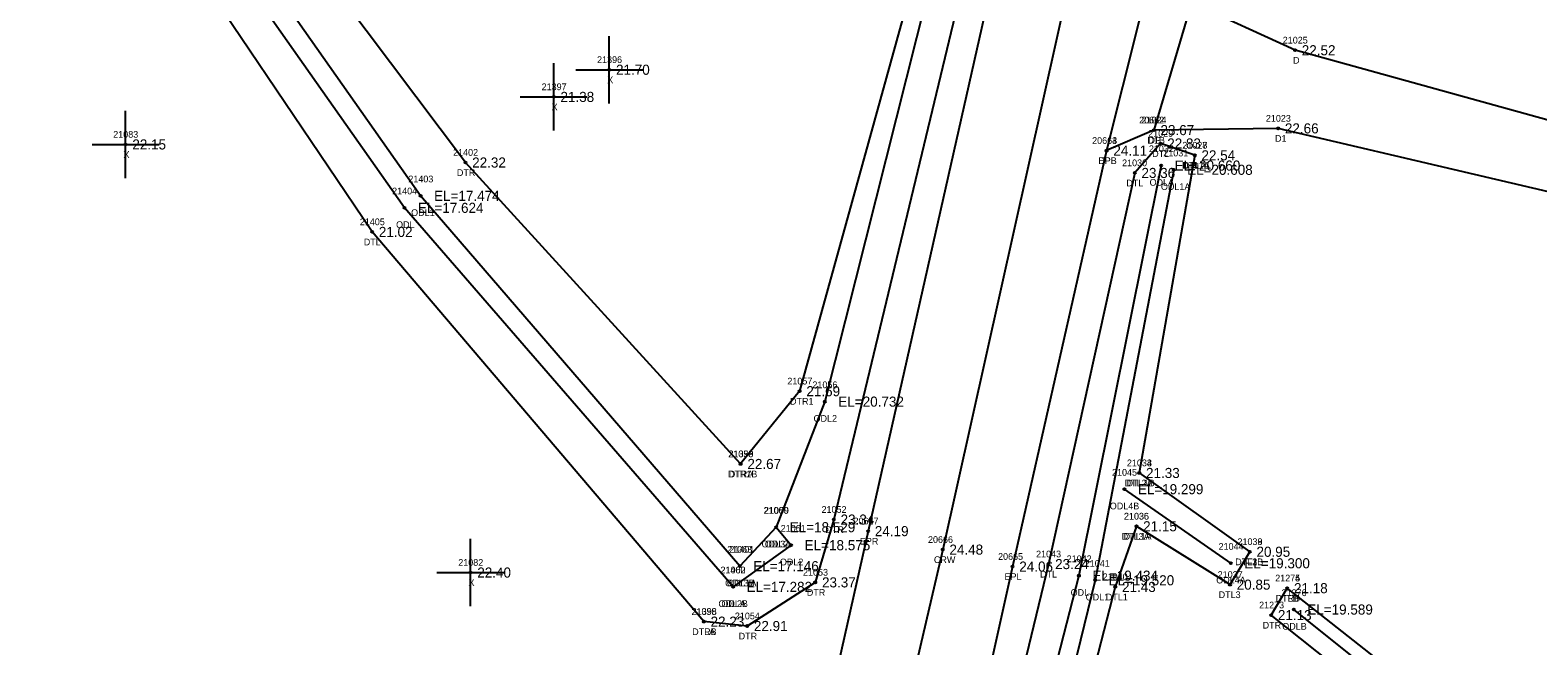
# Model space of a CAD drawing. Extents: x 2655177 to 2656219, y 761780 to 764748.
# Drawn here: x 2655371.8 to 2655596.2, y 762312.5 to 762404.1 of the extents above; entities that cross this region are included whole.
import ezdxf

# ---------------------------------------------------------------- set-up
doc = ezdxf.new("R2010")
doc.units = 0
for name, color, linetype in [('RD_DTM_BkLn1', 7, 'Continuous'), ('RD_EX_Driveway', 7, 'Continuous'), ('RD_EX_Driveway_txCode', 7, 'Continuous'), ('RD_EX_H2O', 7, 'Continuous'), ('RD_EX_H2O_txCode', 7, 'Continuous'), ('RD_EX_Misc', 7, 'Continuous'), ('RD_EX_Misc_txCode', 7, 'Continuous'), ('RD_EX_Road', 7, 'Continuous'), ('RD_EX_Road_txCode', 7, 'Continuous'), ('RD_EX_TX_Driveway_ELEV', 7, 'Continuous'), ('RD_EX_TX_H2O_ELEV', 7, 'Continuous'), ('RD_EX_TX_Misc_ELEV', 7, 'Continuous'), ('RD_EX_TX_Road_ELEV', 7, 'Continuous'), ('RD_HC_Survey_ELEV', 7, 'Continuous'), ('RD_HC_Survey_txCode', 7, 'Continuous'), ('RD_SMD_Locator', 7, 'Continuous')]:
    doc.layers.add(name, color=color, linetype=linetype)

msp = doc.modelspace()

# ---------------------------------------------------------------- linework, layer by layer
at = {"layer": 'RD_DTM_BkLn1'}
msp.add_lwpolyline([(2655711.06, 763230.3), (2655703.38, 763195.9), (2655681.97, 763099.65), (2655659.44, 762998.39), (2655637.72, 762903.26), (2655615.94, 762806.28), (2655593.94, 762710.45), (2655572.67, 762616.37), (2655551.12, 762519.58), (2655528.83, 762422.13), (2655507.58, 762326.81), (2655486.01, 762234.2), (2655464.77, 762141.12), (2655442.2, 762047.28), (2655420.99, 761952.95), (2655398.79, 761855.74), (2655384.11, 761791.21)], dxfattribs=at)
at = {"layer": 'RD_EX_Driveway'}
for points in [[(2655539.15, 762414.81), (2655544.59, 762408.15), (2655538.99, 762389.2), (2655531.98, 762386.15)], [(2655618.28, 762384.97), (2655560.02, 762401.08), (2655544.59, 762408.15)], [(2655615.95, 762375.77), (2655557.51, 762389.46), (2655538.99, 762389.2)]]:
    msp.add_lwpolyline(points, dxfattribs=at)
at = {"layer": 'RD_EX_H2O'}
for p, q in [((2655545.09, 762385.45), (2655536.84, 762338.21)), ((2655536.84, 762338.21), (2655553.28, 762326.49)), ((2655550.47, 762324.78), (2655534.62, 762335.8)), ((2655482.81, 762330.14), (2655477.37, 762324.35))]:
    msp.add_line(p, q, dxfattribs=at)
for points in [[(2655472.03, 762316.1), (2655422.66, 762374.06), (2655364.12, 762460.66), (2655307.09, 762538.82), (2655256.59, 762623.14), (2655196.27, 762713.84), (2655205.8, 762720.91)], [(2655477.51, 762339.55), (2655436.55, 762384.38), (2655373.64, 762467.97), (2655320.48, 762547.58), (2655269.92, 762633.7), (2655205.8, 762720.91)], [(2655476.38, 762321.27), (2655427.48, 762377.64), (2655367.29, 762463.1), (2655312.28, 762542.21), (2655260.75, 762626.43), (2655202.15, 762714.73)], [(2655477.37, 762324.35), (2655429.88, 762379.43), (2655369.67, 762464.93), (2655315.46, 762544.29), (2655265.61, 762630.28), (2655205.06, 762716.28)], [(2655543.55, 762560.68), (2655539.34, 762565), (2655535.47, 762561.26), (2655533.61, 762546.63), (2655528.16, 762524.75), (2655507.6, 762427.4), (2655486.29, 762350.37), (2655477.51, 762339.55)], [(2655543.55, 762560.68), (2655534.37, 762523.92), (2655514.09, 762425.76), (2655491.38, 762331.28), (2655488.62, 762321.94), (2655478.48, 762315.45), (2655472.03, 762316.1)], [(2655538.37, 762560.08), (2655529.54, 762524.52), (2655509.74, 762426.95), (2655490.05, 762348.82), (2655482.81, 762330.14), (2655485.04, 762327.47), (2655476.38, 762321.27)], [(2655545.09, 762385.45), (2655540, 762387.21), (2655536.16, 762382.83), (2655523.31, 762324.66), (2655511.9, 762277.49)], [(2655540.11, 762383.93), (2655527.86, 762322.94), (2655515.9, 762276.48)], [(2655541.96, 762383.3), (2655530.27, 762322.25), (2655518.81, 762275.44)], [(2655536.41, 762330.28), (2655533.27, 762321.26), (2655520.61, 762272.2), (2655514.15, 762273.86), (2655511.9, 762277.49)], [(2655536.41, 762330.28), (2655550.34, 762321.6), (2655553.28, 762326.49)], [(2655458.25, 762004.65), (2655489.16, 762003.6), (2655538.42, 762005.59), (2655556.05, 762013.17), (2655587.88, 762051.39), (2655643.4, 762074.04), (2655655.85, 762091.76), (2655681.86, 762140.14), (2655683.72, 762146.53), (2655664.39, 762201.23), (2655621.98, 762271.36), (2655558.86, 762321.08)], [(2655459.71, 762010.57), (2655488.92, 762008.22), (2655537.08, 762011.25), (2655554.9, 762018.55), (2655583.72, 762054.68), (2655639.44, 762078.76), (2655651.66, 762094.07), (2655673.82, 762140.27), (2655676.22, 762150.22), (2655658.16, 762196.88), (2655618.83, 762267.48), (2655556.47, 762317.07), (2655558.86, 762321.08)], [(2655456.91, 762008.75), (2655489.44, 762005.64), (2655537.92, 762008.34), (2655555.32, 762016.59), (2655585.73, 762052.79), (2655641.23, 762076.72), (2655654.31, 762091.55), (2655679.19, 762140.68), (2655679.13, 762150.47), (2655660.06, 762199), (2655620.4, 762269.42), (2655559.84, 762317.9)]]:
    msp.add_lwpolyline(points, dxfattribs=at)
at = {"layer": 'RD_EX_Misc'}
for p, q in [((2655457.96, 762393.18), (2655457.96, 762403.18)), ((2655449.69, 762389.14), (2655449.69, 762399.14)), ((2655452.96, 762398.18), (2655462.96, 762398.18)), ((2655444.69, 762394.14), (2655454.69, 762394.14)), ((2655385.97, 762382.07), (2655385.97, 762392.07)), ((2655380.97, 762387.07), (2655390.97, 762387.07)), ((2655437.31, 762318.4), (2655437.31, 762328.4)), ((2655432.31, 762323.4), (2655442.31, 762323.4))]:
    msp.add_line(p, q, dxfattribs=at)
at = {"layer": 'RD_EX_Road'}
for points in [[(2655700.99, 763232.28), (2655693.55, 763198.57), (2655671.65, 763102.04), (2655649.04, 763001.06), (2655627.27, 762906.23), (2655605, 762809.37), (2655598.99, 762783.09), (2655583.65, 762714.14), (2655561.97, 762618.32), (2655556.36, 762593.84), (2655548.11, 762557.14), (2655540.1, 762522.48), (2655518.03, 762425.04), (2655496.48, 762329.56), (2655475.55, 762236.62), (2655473.2, 762226.14), (2655466.57, 762197.5), (2655460.06, 762168.16), (2655454.26, 762143.78), (2655432.5, 762049.88), (2655410.7, 761955.51), (2655388.17, 761858.43), (2655373.5, 761793.95)], [(2655576.46, 762583.32), (2655561.41, 762517.24), (2655539.15, 762414.81), (2655531.98, 762386.15), (2655517.98, 762324.29), (2655508.17, 762280.15), (2655501.46, 762251.6), (2655496.92, 762232.09), (2655477.2, 762144.97), (2655472.14, 762122.52), (2655453.74, 762045.1), (2655431.79, 761949.92), (2655409.76, 761853.25), (2655401.25, 761816.42), (2655394.61, 761787.37)]]:
    msp.add_lwpolyline(points, dxfattribs=at)
at = {"layer": 'RD_SMD_Locator'}
for centre in [(2655560.02, 762401.08), (2655457.96, 762398.18), (2655449.69, 762394.14), (2655538.99, 762389.2), (2655538.99, 762389.2), (2655557.51, 762389.46), (2655385.97, 762387.07), (2655540, 762387.21), (2655531.98, 762386.15), (2655531.98, 762386.15), (2655545.09, 762385.45), (2655545.09, 762385.45), (2655436.55, 762384.38), (2655536.16, 762382.83), (2655540.11, 762383.93), (2655541.96, 762383.3), (2655429.88, 762379.43), (2655427.48, 762377.64), (2655422.66, 762374.06), (2655486.29, 762350.37), (2655490.05, 762348.82), (2655477.51, 762339.55), (2655477.51, 762339.55), (2655536.84, 762338.21), (2655536.84, 762338.21), (2655534.62, 762335.8), (2655491.38, 762331.28), (2655482.81, 762330.14), (2655482.81, 762330.14), (2655496.48, 762329.56), (2655536.41, 762330.28), (2655536.41, 762330.28), (2655485.04, 762327.47), (2655507.58, 762326.81), (2655553.28, 762326.49), (2655553.28, 762326.49), (2655477.37, 762324.35), (2655477.37, 762324.35), (2655517.98, 762324.29), (2655523.31, 762324.66), (2655550.47, 762324.78), (2655437.31, 762323.4), (2655488.62, 762321.94), (2655527.86, 762322.94), (2655530.27, 762322.25), (2655476.38, 762321.27), (2655476.38, 762321.27), (2655533.27, 762321.26), (2655550.34, 762321.6), (2655558.86, 762321.08), (2655558.86, 762321.08), (2655559.84, 762317.9), (2655472.03, 762316.1), (2655472.03, 762316.1), (2655478.48, 762315.45), (2655556.47, 762317.07)]:
    msp.add_circle(centre, 0.15, dxfattribs=at)

# ---------------------------------------------------------------- texts
at = {"layer": 'RD_EX_Driveway_txCode'}
for s, p in [('21025', (2655558.19, 762402.08)), ('D', (2655559.72, 762399.08)), ('21023', (2655555.68, 762390.46)), ('20662', (2655536.82, 762390.2)), ('21024', (2655537.16, 762390.2)), ('20663', (2655529.82, 762387.15)), ('D1B', (2655538.05, 762387.2)), ('DP', (2655538.21, 762387.2)), ('D1', (2655557.04, 762387.46)), ('DPB', (2655530.73, 762384.15))]:
    msp.add_text(s, height=1, dxfattribs=at).set_placement(p)
at = {"layer": 'RD_EX_H2O_txCode'}
for s, p in [('21029', (2655538.17, 762388.21)), ('21032', (2655538.27, 762385.93)), ('21027', (2655543.25, 762386.45)), ('21028', (2655543.25, 762386.45)), ('21402', (2655434.71, 762385.38)), ('21030', (2655534.28, 762383.83)), ('DTL', (2655538.76, 762385.21)), ('21031', (2655540.41, 762385.3)), ('21403', (2655428.05, 762381.43)), ('DTR', (2655435.28, 762382.38)), ('DTL1A', (2655543.19, 762383.45)), ('DTLA', (2655543.35, 762383.45)), ('21404', (2655425.64, 762379.64)), ('DTL', (2655534.91, 762380.83)), ('ODLA', (2655538.37, 762380.93)), ('ODL1A', (2655540.06, 762380.3)), ('21405', (2655420.83, 762375.06)), ('ODL1', (2655428.47, 762376.43)), ('ODL', (2655426.23, 762374.64)), ('DTL', (2655421.42, 762372.06)), ('21057', (2655484.46, 762351.37)), ('21056', (2655488.19, 762350.82)), ('DTR1', (2655484.86, 762348.37)), ('ODL2', (2655488.36, 762345.82)), ('21058', (2655475.67, 762340.55)), ('21399', (2655475.71, 762340.55)), ('21033', (2655535, 762339.21)), ('21034', (2655535, 762339.21)), ('DTR1B', (2655475.6, 762337.55)), ('DTRA', (2655475.75, 762337.55)), ('21045', (2655532.78, 762337.8)), ('DTL2A', (2655534.66, 762336.21)), ('DTL1B', (2655534.95, 762336.21)), ('21060', (2655480.91, 762332.14)), ('21059', (2655480.98, 762332.14)), ('21052', (2655489.55, 762332.28)), ('ODL4B', (2655532.45, 762332.8)), ('21036', (2655534.55, 762331.28)), ('21035', (2655534.57, 762331.28)), ('21061', (2655483.47, 762329.47)), ('DTR', (2655490.11, 762329.28)), ('DTL3A', (2655534.22, 762328.28)), ('DTL1A', (2655534.51, 762328.28)), ('21063', (2655475.51, 762326.35)), ('21401', (2655475.82, 762326.35)), ('ODL3A', (2655480.63, 762327.14)), ('ODL2', (2655481.12, 762327.14)), ('21043', (2655521.48, 762325.66)), ('21044', (2655548.64, 762326.78)), ('21038', (2655551.45, 762327.49)), ('21039', (2655551.45, 762327.49)), ('21400', (2655474.5, 762323.27)), ('21062', (2655474.52, 762323.27)), ('ODL2', (2655483.35, 762324.47)), ('21042', (2655526.03, 762324.94)), ('21041', (2655528.72, 762324.25)), ('DTL2B', (2655551.12, 762324.49)), ('DTL3B', (2655551.12, 762324.49)), ('ODL3B', (2655475.2, 762321.35)), ('ODL1A', (2655475.47, 762321.35)), ('21053', (2655486.79, 762322.94)), ('DTL', (2655522.07, 762322.66)), ('21040', (2655531.39, 762322.26)), ('ODL4A', (2655548.29, 762321.78)), ('21037', (2655548.51, 762322.6)), ('21274', (2655557.07, 762322.08)), ('21275', (2655557.07, 762322.08)), ('DTR', (2655487.36, 762319.94)), ('ODL', (2655526.62, 762319.94)), ('ODL1', (2655528.86, 762319.25)), ('DTL1', (2655531.86, 762319.26)), ('DTL3', (2655548.65, 762319.6)), ('DTRB', (2655557.12, 762319.08)), ('DTLB', (2655557.15, 762319.08)), ('21276', (2655558.02, 762319.9)), ('21055', (2655470.19, 762317.1)), ('21398', (2655470.23, 762317.1)), ('ODL2B', (2655474.21, 762318.27)), ('ODLA', (2655474.65, 762318.27)), ('21054', (2655476.65, 762316.45)), ('21273', (2655554.67, 762318.07)), ('DTR', (2655555.2, 762315.07)), ('ODLB', (2655558.12, 762314.9)), ('DTRB', (2655470.29, 762314.1)), ('DTLA', (2655470.3, 762314.1)), ('DTR', (2655477.21, 762313.45))]:
    msp.add_text(s, height=1, dxfattribs=at).set_placement(p)
at = {"layer": 'RD_EX_Misc_txCode'}
for s, p in [('21396', (2655456.14, 762399.18)), ('21397', (2655447.89, 762395.14)), ('X', (2655457.65, 762396.18)), ('X', (2655449.37, 762392.14)), ('21083', (2655384.13, 762388.07)), ('X', (2655385.65, 762385.07)), ('21082', (2655435.48, 762324.4)), ('X', (2655437, 762321.4))]:
    msp.add_text(s, height=1, dxfattribs=at).set_placement(p)
at = {"layer": 'RD_EX_Road_txCode'}
for s, p in [('20664', (2655529.82, 762387.15)), ('EPL', (2655530.78, 762384.15)), ('20667', (2655494.31, 762330.56)), ('EPR', (2655495.25, 762327.56)), ('20665', (2655515.82, 762325.29)), ('EPL', (2655516.78, 762322.29))]:
    msp.add_text(s, height=1, dxfattribs=at).set_placement(p)
at = {"layer": 'RD_EX_TX_Driveway_ELEV'}
for s, p in [('22.52', (2655561.02, 762400.33)), ('23.67', (2655539.99, 762388.45)), ('23.67', (2655539.99, 762388.45)), ('22.66', (2655558.51, 762388.71)), ('24.11', (2655532.98, 762385.4))]:
    msp.add_text(s, height=1.5, dxfattribs=at).set_placement(p)
at = {"layer": 'RD_EX_TX_H2O_ELEV'}
for s, p in [('22.83', (2655541, 762386.46)), ('22.32', (2655437.55, 762383.63)), ('EL=20.660', (2655542.11, 762383.18)), ('22.54', (2655546.09, 762384.7)), ('22.54', (2655546.09, 762384.7)), ('23.36', (2655537.16, 762382.08)), ('EL=20.608', (2655543.96, 762382.55)), ('EL=17.624', (2655429.48, 762376.89)), ('EL=17.474', (2655431.88, 762378.68)), ('21.02', (2655423.66, 762373.31)), ('21.69', (2655487.29, 762349.62)), ('EL=20.732', (2655492.05, 762348.07)), ('22.67', (2655478.51, 762338.8)), ('22.67', (2655478.51, 762338.8)), ('21.33', (2655537.84, 762337.46)), ('21.33', (2655537.84, 762337.46)), ('EL=19.299', (2655536.62, 762335.05)), ('EL=18.529', (2655484.81, 762329.39)), ('EL=18.529', (2655484.81, 762329.39)), ('23.34', (2655492.38, 762330.53)), ('21.15', (2655537.41, 762329.53)), ('21.15', (2655537.41, 762329.53)), ('EL=18.575', (2655487.04, 762326.72)), ('20.95', (2655554.28, 762325.74)), ('20.95', (2655554.28, 762325.74)), ('EL=17.146', (2655479.37, 762323.6)), ('EL=17.146', (2655479.37, 762323.6)), ('23.24', (2655524.31, 762323.91)), ('EL=19.300', (2655552.47, 762324.03)), ('EL=17.282', (2655478.38, 762320.52)), ('EL=17.282', (2655478.38, 762320.52)), ('23.37', (2655489.62, 762321.19)), ('EL=19.434', (2655529.86, 762322.19)), ('EL=19.520', (2655532.27, 762321.5)), ('21.43', (2655534.27, 762320.51)), ('20.85', (2655551.34, 762320.85)), ('21.18', (2655559.86, 762320.33)), ('21.18', (2655559.86, 762320.33)), ('21.13', (2655557.47, 762316.32)), ('EL=19.589', (2655561.84, 762317.15)), ('22.23', (2655473.03, 762315.35)), ('22.23', (2655473.03, 762315.35)), ('22.91', (2655479.48, 762314.7))]:
    msp.add_text(s, height=1.5, dxfattribs=at).set_placement(p)
at = {"layer": 'RD_EX_TX_Misc_ELEV'}
for s, p in [('21.70', (2655458.96, 762397.43)), ('21.38', (2655450.69, 762393.39)), ('22.15', (2655386.97, 762386.32)), ('22.40', (2655438.31, 762322.65))]:
    msp.add_text(s, height=1.5, dxfattribs=at).set_placement(p)
at = {"layer": 'RD_EX_TX_Road_ELEV'}
for s, p in [('24.11', (2655532.98, 762385.4)), ('24.19', (2655497.48, 762328.81)), ('24.06', (2655518.98, 762323.54))]:
    msp.add_text(s, height=1.5, dxfattribs=at).set_placement(p)
at = {"layer": 'RD_HC_Survey_ELEV'}
msp.add_text('24.48', height=1.5, dxfattribs=at).set_placement((2655508.58, 762326.06))
at = {"layer": 'RD_HC_Survey_txCode'}
for s, p in [('20666', (2655505.39, 762327.81)), ('CRW', (2655506.27, 762324.81))]:
    msp.add_text(s, height=1, dxfattribs=at).set_placement(p)

doc.saveas('drawing.dxf')
